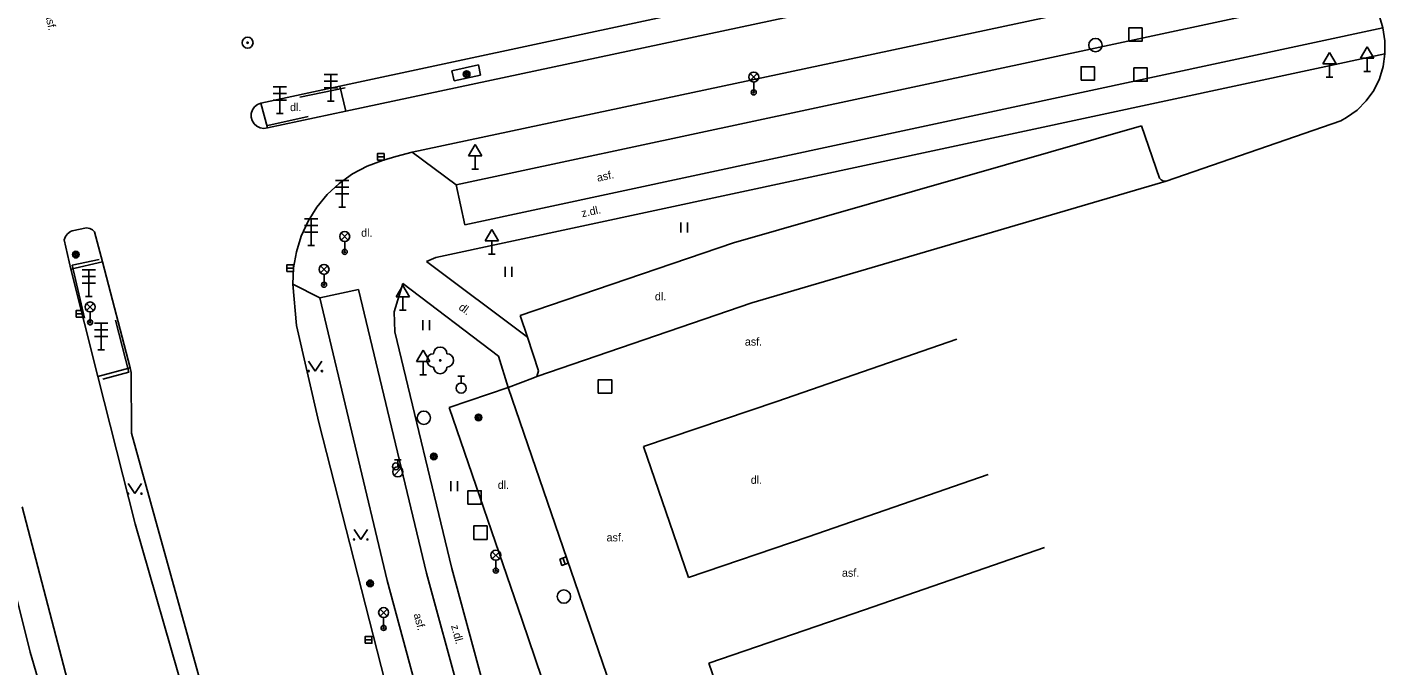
# Model space of a CAD drawing. Extents: x -640201 to -639641, y -1044739 to -1044317.
# Drawn here: x -640090.1 to -639988.3, y -1044666.3 to -1044618.5 of the extents above; entities that cross this region are included whole.
import ezdxf

# ---------------------------------------------------------------- set-up
doc = ezdxf.new("R2010")
doc.units = 0
for name, color, linetype in [('Pol_bod_pole', 7, 'Continuous'), ('Popis povrchů', 7, 'Continuous'), ('Rozhraní ploch 1', 7, 'Continuous'), ('Rozhraní ploch 2', 7, 'Continuous'), ('Sloupy_označník', 7, 'Continuous'), ('Svodidla_zábr_', 7, 'Continuous'), ('Zeleň - stromy', 7, 'Continuous'), ('Znaky doprava', 7, 'Continuous'), ('Znaky kanalizace', 7, 'Continuous'), ('Znaky voda', 7, 'Continuous'), ('Značky doprava', 7, 'Continuous'), ('Značky KM', 7, 'Continuous'), ('Šachty ner_', 7, 'Continuous')]:
    doc.layers.add(name, color=color, linetype=linetype)

msp = doc.modelspace()

# ---------------------------------------------------------------- linework, layer by layer
at = {"layer": 'Pol_bod_pole'}
for radius in [0.412, 0.05]:
    msp.add_circle((-640073.54, -1044619.66), radius, dxfattribs=at)
at = {"layer": 'Rozhraní ploch 1'}
for p, q in [((-640003.85, -1044609.46), (-640066.63, -1044622.91)), ((-640003.36, -1044611.41), (-640066.18, -1044624.78)), ((-640061.2, -1044627.86), (-639995.6, -1044613.9)), ((-640057.91, -1044630.3), (-639989.92, -1044615.76)), ((-639988.3, -1044620.49), (-640059.43, -1044635.74)), ((-640066.63, -1044622.91), (-640072.54, -1044624.19)), ((-640066.63, -1044622.91), (-640066.18, -1044624.78)), ((-640072.04, -1044626.04), (-640072.54, -1044624.19)), ((-640066.18, -1044624.78), (-640072.04, -1044626.04)), ((-640006.55, -1044625.89), (-640037.11, -1044634.65)), ((-640005.18, -1044629.8), (-640006.55, -1044625.89)), ((-639991.6, -1044625.5), (-640004.69, -1044630.03)), ((-640063.35, -1044628.45), (-640062.43, -1044628.18)), ((-640062.43, -1044628.18), (-640061.2, -1044627.86)), ((-640061.2, -1044627.86), (-640057.91, -1044630.3)), ((-640035.75, -1044639.16), (-640004.69, -1044630.03)), ((-640085.6, -1044633.54), (-640086.68, -1044633.75)), ((-640086.78, -1044636.62), (-640087.29, -1044634.44)), ((-640084.42, -1044636.07), (-640085, -1044633.83)), ((-640086.78, -1044636.62), (-640084.42, -1044636.07)), ((-640082.34, -1044644.02), (-640084.42, -1044636.07)), ((-640059.43, -1044635.74), (-640060.12, -1044636.06)), ((-640060.12, -1044636.06), (-640052.56, -1044641.72)), ((-640084.77, -1044644.68), (-640086.78, -1044636.62)), ((-640070.14, -1044637.76), (-640069.871, -1044640.845)), ((-640070.14, -1044637.76), (-640068.12, -1044638.78)), ((-640061.9, -1044637.71), (-640062.56, -1044639.82)), ((-640054.74, -1044643.14), (-640061.9, -1044637.71)), ((-640068.12, -1044638.78), (-640063.08, -1044659.96)), ((-640051.85, -1044644.67), (-640035.75, -1044639.16)), ((-640062.56, -1044639.82), (-640062.5, -1044641.31)), ((-640068.188, -1044648.124), (-640069.871, -1044640.845)), ((-640062.5, -1044641.31), (-640058.24, -1044659.05)), ((-640033.87, -1044646.54), (-640020.381, -1044641.869)), ((-640054.74, -1044643.14), (-640054.01, -1044645.5)), ((-640084.77, -1044644.68), (-640082.34, -1044644.02)), ((-640084.77, -1044644.68), (-640081.959, -1044655.701)), ((-640082.26, -1044644.37), (-640082.34, -1044644.02)), ((-640082.23, -1044648.92), (-640082.26, -1044644.37)), ((-640054.01, -1044645.5), (-640041.7, -1044681.34)), ((-640093.96, -1044648.81), (-640089.84, -1044665.33)), ((-640062.438, -1044670.647), (-640068.188, -1044648.124)), ((-640082.23, -1044648.92), (-640080.485, -1044655.222)), ((-640031.53, -1044656.68), (-640018.041, -1044652.009)), ((-640086.744, -1044668.595), (-640090.444, -1044654.429)), ((-640081.959, -1044655.701), (-640076.071, -1044676.224)), ((-640080.485, -1044655.222), (-640074.751, -1044675.954)), ((-640027.297, -1044662.148), (-640013.808, -1044657.477)), ((-640063.08, -1044659.96), (-640057.53, -1044680.47)), ((-640058.24, -1044659.05), (-640052.89, -1044678.8)), ((-640089.84, -1044665.33), (-640084.555, -1044683.025))]:
    msp.add_line(p, q, dxfattribs=at)
for points in [[(-639988.45, -1044618.54), (-639988.682, -1044617.781), (-639989.008, -1044617.056), (-639989.423, -1044616.379), (-639989.92, -1044615.76)], [(-639988.3, -1044620.49), (-639988.3, -1044619.509), (-639988.45, -1044618.54)], [(-639988.3, -1044620.49), (-639988.423, -1044621.432), (-639988.703, -1044622.362), (-639989.131, -1044623.232), (-639989.696, -1044624.021), (-639990.383, -1044624.706), (-639991.173, -1044625.269), (-639991.6, -1044625.5)], [(-640072.54, -1044624.19), (-640072.797, -1044624.292), (-640073.013, -1044624.464), (-640073.172, -1044624.69), (-640073.26, -1044624.952), (-640073.269, -1044625.228), (-640073.2, -1044625.495), (-640073.057, -1044625.731), (-640072.852, -1044625.917), (-640072.603, -1044626.037), (-640072.331, -1044626.081), (-640072.04, -1044626.04)], [(-640065.665, -1044629.485), (-640064.58, -1044628.907), (-640063.429, -1044628.474), (-640063.35, -1044628.45)], [(-640070.14, -1044637.76), (-640070.09, -1044636.531), (-640069.881, -1044635.319), (-640069.517, -1044634.145), (-640069, -1044633.02), (-640068.35, -1044631.986), (-640067.566, -1044631.038), (-640066.666, -1044630.2), (-640065.665, -1044629.485)], [(-640005.18, -1044629.8), (-640005.055, -1044629.944), (-640004.882, -1044630.026), (-640004.69, -1044630.03)], [(-640085.6, -1044633.54), (-640085.36, -1044633.57), (-640085.157, -1044633.672), (-640085, -1044633.83)], [(-640087.29, -1044634.44), (-640087.198, -1044634.185), (-640087.035, -1044633.969), (-640086.817, -1044633.809), (-640086.68, -1044633.75)], [(-640037.11, -1044634.65), (-640053.11, -1044640.1)], [(-640053.11, -1044640.1), (-640052.56, -1044641.72), (-640051.74, -1044644.24), (-640051.85, -1044644.67), (-640052.17, -1044644.79), (-640054.01, -1044645.5)], [(-640054.01, -1044645.5), (-640058.44, -1044646.99)], [(-640043.87, -1044649.91), (-640033.87, -1044646.54)], [(-640058.44, -1044646.99), (-640052.96, -1044662.93)], [(-640040.5, -1044659.73), (-640043.87, -1044649.91)], [(-640031.53, -1044656.68), (-640040.5, -1044659.73)], [(-640052.96, -1044662.93), (-640046.17, -1044682.96)], [(-640038.96, -1044666.15), (-640027.297, -1044662.148)], [(-640035.58, -1044676), (-640038.96, -1044666.15)]]:
    msp.add_lwpolyline(points, dxfattribs=at)
at = {"layer": 'Rozhraní ploch 2'}
for p, q in [((-640057.25, -1044633.31), (-639988.45, -1044618.54)), ((-640058.22, -1044621.76), (-640056.24, -1044621.32)), ((-640056.08, -1044622.08), (-640056.24, -1044621.32)), ((-640058.06, -1044622.52), (-640058.22, -1044621.76)), ((-640056.08, -1044622.08), (-640058.06, -1044622.52)), ((-640057.91, -1044630.3), (-640057.25, -1044633.31)), ((-640068.12, -1044638.78), (-640065.23, -1044638.15)), ((-640065.23, -1044638.15), (-640060.12, -1044659.4)), ((-640060.12, -1044659.4), (-640054.68, -1044679.45))]:
    msp.add_line(p, q, dxfattribs=at)
at = {"layer": 'Sloupy_označník'}
for centre, radius in [((-640057.12, -1044622.02), 0.25), ((-640057.12, -1044622.02), 0.158), ((-640057.12, -1044622.02), 0.05), ((-640086.416, -1044635.537), 0.25), ((-640086.416, -1044635.537), 0.158), ((-640086.416, -1044635.537), 0.05), ((-640056.23, -1044647.74), 0.25), ((-640056.23, -1044647.74), 0.158), ((-640056.23, -1044647.74), 0.05), ((-640059.58, -1044650.66), 0.25), ((-640059.58, -1044650.66), 0.158), ((-640059.58, -1044650.66), 0.05), ((-640064.36, -1044660.17), 0.25), ((-640064.36, -1044660.17), 0.158), ((-640064.36, -1044660.17), 0.05)]:
    msp.add_circle(centre, radius, dxfattribs=at)
at = {"layer": 'Svodidla_zábr_'}
for p, q in [((-640066.23, -1044623.03), (-640069.63, -1044623.74)), ((-640069.01, -1044625.19), (-640072.03, -1044625.85)), ((-640086.68, -1044636.32), (-640084.66, -1044635.89)), ((-640085.76, -1044640.3), (-640086.68, -1044636.32)), ((-640082.45, -1044644.35), (-640083.44, -1044640.44)), ((-640084.4, -1044644.87), (-640082.45, -1044644.35))]:
    msp.add_line(p, q, dxfattribs=at)
at = {"layer": 'Zeleň - stromy'}
msp.add_circle((-640059.1, -1044643.46), 0.05, dxfattribs=at)
for centre, start, end in [((-640059.1, -1044642.96), 0, 180), ((-640059.6, -1044643.46), 90, 270), ((-640058.6, -1044643.46), 270, 90), ((-640059.1, -1044643.96), 180, 0)]:
    msp.add_arc(centre, 0.5, start, end, dxfattribs=at)
at = {"layer": 'Znaky doprava'}
for p, q in [((-640067.81, -1044622.05), (-640066.81, -1044622.05)), ((-640067.31, -1044622.05), (-640067.31, -1044624.05)), ((-640035.865, -1044621.965), (-640035.335, -1044622.495)), ((-640035.865, -1044622.495), (-640035.335, -1044621.965)), ((-640071.63, -1044622.97), (-640070.63, -1044622.97)), ((-640071.13, -1044622.97), (-640071.13, -1044624.97)), ((-640067.81, -1044622.55), (-640066.81, -1044622.55)), ((-640066.81, -1044623.05), (-640067.81, -1044623.05)), ((-640035.6, -1044623.38), (-640035.6, -1044622.605)), ((-640071.63, -1044623.47), (-640070.63, -1044623.47)), ((-640070.63, -1044623.97), (-640071.63, -1044623.97)), ((-640067.56, -1044624.05), (-640067.06, -1044624.05)), ((-640071.38, -1044624.97), (-640070.88, -1044624.97)), ((-640066.94, -1044629.99), (-640065.94, -1044629.99)), ((-640066.94, -1044630.49), (-640065.94, -1044630.49)), ((-640066.44, -1044629.99), (-640066.44, -1044631.99)), ((-640065.94, -1044630.99), (-640066.94, -1044630.99)), ((-640066.69, -1044631.99), (-640066.19, -1044631.99)), ((-640069.27, -1044632.85), (-640068.27, -1044632.85)), ((-640069.27, -1044633.35), (-640068.27, -1044633.35)), ((-640068.77, -1044632.85), (-640068.77, -1044634.85)), ((-640068.27, -1044633.85), (-640069.27, -1044633.85)), ((-640066.525, -1044633.915), (-640065.995, -1044634.445)), ((-640066.525, -1044634.445), (-640065.995, -1044633.915)), ((-640066.26, -1044635.33), (-640066.26, -1044634.555)), ((-640069.02, -1044634.85), (-640068.52, -1044634.85)), ((-640068.075, -1044636.375), (-640067.545, -1044636.905)), ((-640068.075, -1044636.905), (-640067.545, -1044636.375)), ((-640085.94, -1044636.67), (-640084.94, -1044636.67)), ((-640085.94, -1044637.17), (-640084.94, -1044637.17)), ((-640085.44, -1044636.67), (-640085.44, -1044638.67)), ((-640067.81, -1044637.79), (-640067.81, -1044637.015)), ((-640084.94, -1044637.67), (-640085.94, -1044637.67)), ((-640085.69, -1044638.67), (-640085.19, -1044638.67)), ((-640085.605, -1044639.195), (-640085.075, -1044639.725)), ((-640085.605, -1044639.725), (-640085.075, -1044639.195)), ((-640085.34, -1044640.61), (-640085.34, -1044639.835)), ((-640085.01, -1044640.67), (-640084.01, -1044640.67)), ((-640084.51, -1044640.67), (-640084.51, -1044642.67)), ((-640085.01, -1044641.17), (-640084.01, -1044641.17)), ((-640084.01, -1044641.67), (-640085.01, -1044641.67)), ((-640084.76, -1044642.67), (-640084.26, -1044642.67)), ((-640055.195, -1044657.795), (-640054.665, -1044658.325)), ((-640055.195, -1044658.325), (-640054.665, -1044657.795)), ((-640054.93, -1044659.21), (-640054.93, -1044658.435)), ((-640063.605, -1044662.095), (-640063.075, -1044662.625)), ((-640063.605, -1044662.625), (-640063.075, -1044662.095)), ((-640063.34, -1044663.51), (-640063.34, -1044662.735))]:
    msp.add_line(p, q, dxfattribs=at)
for centre, radius in [((-640035.6, -1044622.23), 0.375), ((-640035.6, -1044623.38), 0.19), ((-640035.6, -1044623.38), 0.05), ((-640066.26, -1044634.18), 0.375), ((-640066.26, -1044635.33), 0.19), ((-640066.26, -1044635.33), 0.05), ((-640067.81, -1044636.64), 0.375), ((-640067.81, -1044637.79), 0.19), ((-640067.81, -1044637.79), 0.05), ((-640085.34, -1044639.46), 0.375), ((-640085.34, -1044640.61), 0.19), ((-640085.34, -1044640.61), 0.05), ((-640054.93, -1044658.06), 0.375), ((-640054.93, -1044659.21), 0.19), ((-640054.93, -1044659.21), 0.05), ((-640063.34, -1044662.36), 0.375), ((-640063.34, -1044663.51), 0.19), ((-640063.34, -1044663.51), 0.05)]:
    msp.add_circle(centre, radius, dxfattribs=at)
at = {"layer": 'Znaky kanalizace'}
for p, q in [((-640063.81, -1044628.22), (-640063.31, -1044628.22)), ((-640070.6, -1044636.56), (-640070.1, -1044636.56)), ((-640086.39, -1044639.98), (-640085.89, -1044639.98)), ((-640049.901, -1044658.264), (-640049.739, -1044658.736)), ((-640064.72, -1044664.4), (-640064.22, -1044664.4))]:
    msp.add_line(p, q, dxfattribs=at)
for points in [[(-640063.81, -1044628.47), (-640063.31, -1044628.47), (-640063.31, -1044627.97), (-640063.81, -1044627.97)], [(-640070.6, -1044636.81), (-640070.1, -1044636.81), (-640070.1, -1044636.31), (-640070.6, -1044636.31)], [(-640086.39, -1044640.23), (-640085.89, -1044640.23), (-640085.89, -1044639.73), (-640086.39, -1044639.73)], [(-640050.138, -1044658.345), (-640049.975, -1044658.818), (-640049.502, -1044658.655), (-640049.665, -1044658.182)], [(-640064.72, -1044664.65), (-640064.22, -1044664.65), (-640064.22, -1044664.15), (-640064.72, -1044664.15)]]:
    msp.add_lwpolyline(points, close=True, dxfattribs=at)
for centre in [(-640009.99, -1044619.84), (-640060.33, -1044647.76), (-640049.83, -1044661.16)]:
    msp.add_circle(centre, 0.5, dxfattribs=at)
at = {"layer": 'Znaky voda'}
for p, q in [((-640057.78, -1044644.641), (-640057.28, -1044644.641)), ((-640057.53, -1044645.165), (-640057.53, -1044644.641)), ((-640062.545, -1044652.075), (-640062.015, -1044651.545)), ((-640062.53, -1044650.91), (-640062.03, -1044650.91)), ((-640062.28, -1044651.435), (-640062.28, -1044650.91))]:
    msp.add_line(p, q, dxfattribs=at)
for centre, radius in [((-640057.53, -1044645.54), 0.375), ((-640062.42, -1044651.4), 0.25), ((-640062.28, -1044651.81), 0.375)]:
    msp.add_circle(centre, radius, dxfattribs=at)
at = {"layer": 'Značky doprava'}
for p, q in [((-639990.12, -1044620.81), (-639989.62, -1044619.96)), ((-639989.62, -1044619.96), (-639989.12, -1044620.81)), ((-639992.95, -1044621.25), (-639992.45, -1044620.4)), ((-639992.95, -1044621.25), (-639991.95, -1044621.25)), ((-639992.45, -1044620.4), (-639991.95, -1044621.25)), ((-639992.45, -1044622.25), (-639992.45, -1044621.25)), ((-639990.12, -1044620.81), (-639989.12, -1044620.81)), ((-639989.62, -1044621.81), (-639989.62, -1044620.81)), ((-639992.7, -1044622.25), (-639992.2, -1044622.25)), ((-639989.87, -1044621.81), (-639989.37, -1044621.81)), ((-640056.99, -1044628.13), (-640056.49, -1044627.28)), ((-640056.49, -1044627.28), (-640055.99, -1044628.13)), ((-640056.99, -1044628.13), (-640055.99, -1044628.13)), ((-640056.49, -1044629.13), (-640056.49, -1044628.13)), ((-640056.74, -1044629.13), (-640056.24, -1044629.13)), ((-640055.72, -1044634.5), (-640055.22, -1044633.65)), ((-640055.72, -1044634.5), (-640054.72, -1044634.5)), ((-640055.22, -1044633.65), (-640054.72, -1044634.5)), ((-640055.22, -1044635.5), (-640055.22, -1044634.5)), ((-640055.47, -1044635.5), (-640054.97, -1044635.5)), ((-640062.4, -1044638.7), (-640061.9, -1044637.85)), ((-640061.9, -1044637.85), (-640061.4, -1044638.7)), ((-640062.4, -1044638.7), (-640061.4, -1044638.7)), ((-640061.9, -1044639.7), (-640061.9, -1044638.7)), ((-640062.15, -1044639.7), (-640061.65, -1044639.7)), ((-640060.88, -1044643.55), (-640060.38, -1044642.7)), ((-640060.38, -1044642.7), (-640059.88, -1044643.55)), ((-640060.88, -1044643.55), (-640059.88, -1044643.55)), ((-640060.38, -1044644.55), (-640060.38, -1044643.55)), ((-640060.63, -1044644.55), (-640060.13, -1044644.55))]:
    msp.add_line(p, q, dxfattribs=at)
at = {"layer": 'Značky KM'}
for p, q in [((-640041.067, -1044633.89), (-640041.067, -1044633.14)), ((-640040.567, -1044633.89), (-640040.567, -1044633.14)), ((-640054.244, -1044637.204), (-640054.244, -1044636.454)), ((-640053.744, -1044637.204), (-640053.744, -1044636.454)), ((-640060.401, -1044641.202), (-640060.401, -1044640.452)), ((-640059.901, -1044641.202), (-640059.901, -1044640.452)), ((-640068.97, -1044643.51), (-640068.47, -1044644.26)), ((-640068.47, -1044644.26), (-640067.97, -1044643.51)), ((-640082.49, -1044652.69), (-640081.99, -1044653.44)), ((-640081.99, -1044653.44), (-640081.49, -1044652.69)), ((-640058.313, -1044653.269), (-640058.313, -1044652.519)), ((-640057.813, -1044653.269), (-640057.813, -1044652.519)), ((-640065.551, -1044656.131), (-640065.051, -1044656.881)), ((-640065.051, -1044656.881), (-640064.551, -1044656.131))]:
    msp.add_line(p, q, dxfattribs=at)
for centre in [(-640068.97, -1044644.26), (-640067.97, -1044644.26), (-640082.49, -1044653.44), (-640081.49, -1044653.44), (-640065.551, -1044656.881), (-640064.551, -1044656.881)]:
    msp.add_circle(centre, 0.05, dxfattribs=at)
at = {"layer": 'Šachty ner_'}
for points in [[(-640007.5, -1044619.55), (-640006.5, -1044619.55), (-640006.5, -1044618.55), (-640007.5, -1044618.55)], [(-640011.07, -1044622.46), (-640010.07, -1044622.46), (-640010.07, -1044621.46), (-640011.07, -1044621.46)], [(-640007.11, -1044622.55), (-640006.11, -1044622.55), (-640006.11, -1044621.55), (-640007.11, -1044621.55)], [(-640047.25, -1044645.91), (-640046.25, -1044645.91), (-640046.25, -1044644.91), (-640047.25, -1044644.91)], [(-640057.02, -1044654.23), (-640056.02, -1044654.23), (-640056.02, -1044653.23), (-640057.02, -1044653.23)], [(-640056.59, -1044656.87), (-640055.59, -1044656.87), (-640055.59, -1044655.87), (-640056.59, -1044655.87)]]:
    msp.add_lwpolyline(points, close=True, dxfattribs=at)

# ---------------------------------------------------------------- texts
at = {"layer": 'Popis povrchů'}
for s, rotation, p in [('asf.', 283.17644, (-640088.732, -1044617.531)), ('asf.', 12.10783, (-640047.294, -1044630.079)), ('z.dl.', 12.11621, (-640048.45, -1044632.742)), ('dl.', 323.17864, (-640057.769, -1044639.595)), ('asf.', 285.1416, (-640061.104, -1044662.496)), ('z.dl.', 285.18013, (-640058.295, -1044663.351))]:
    msp.add_text(s, height=0.6, rotation=rotation, dxfattribs=at).set_placement(p)
for s, p in [('dl.', (-640070.356, -1044624.783)), ('dl.', (-640065.024, -1044634.198)), ('dl.', (-640043.008, -1044638.967)), ('asf.', (-640036.266, -1044642.355)), ('dl.', (-640054.79, -1044653.086)), ('dl.', (-640035.825, -1044652.708)), ('asf.', (-640046.631, -1044657.026)), ('asf.', (-640028.989, -1044659.674))]:
    msp.add_text(s, height=0.6, dxfattribs=at).set_placement(p)

doc.saveas('drawing.dxf')
